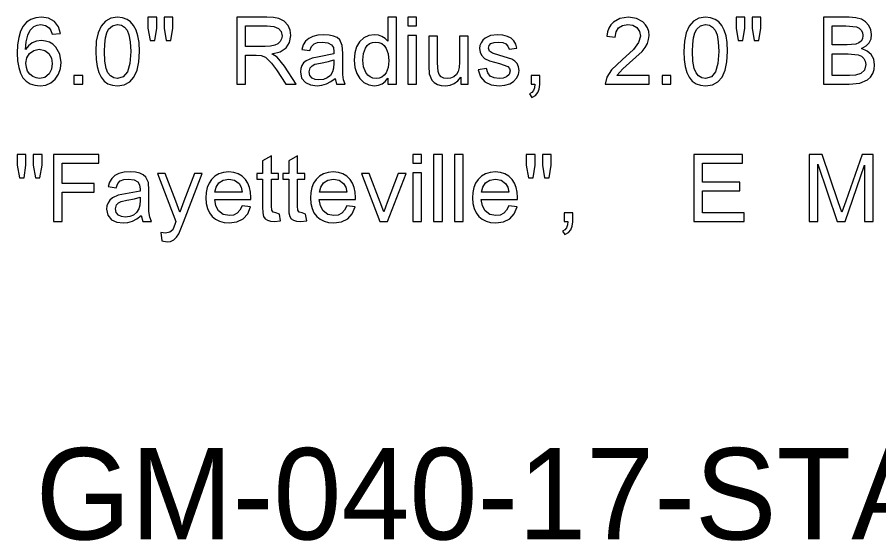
# Model space of a CAD drawing. Extents: x 620864 to 620948.6, y 415499.7 to 415559.1.
# Drawn here: x 620863.977 to 620867.745, y 415533.248 to 415535.538 of the extents above; entities that cross this region are included whole.
import ezdxf

# ---------------------------------------------------------------- set-up
doc = ezdxf.new("R2010")
doc.units = 0
doc.layers.add('SIGNS', color=7, linetype='Continuous')

msp = doc.modelspace()

# ---------------------------------------------------------------- linework, layer by layer
at = {"layer": 'SIGNS'}
for points in [[(620864.1658, 415535.4666), (620864.1569, 415535.4965), (620864.1392, 415535.5191), (620864.1138, 415535.5332), (620864.0822, 415535.538), (620864.0574, 415535.5356), (620864.036, 415535.5282), (620864.0177, 415535.5158), (620864.0029, 415535.4986), (620863.9913, 415535.4764), (620863.9832, 415535.4494), (620863.9782, 415535.4174), (620863.9766, 415535.3806), (620863.9781, 415535.3471), (620863.9829, 415535.3181), (620863.9908, 415535.2936), (620864.0018, 415535.2736), (620864.0159, 415535.258), (620864.0332, 415535.2469), (620864.0537, 415535.2403), (620864.0773, 415535.2381), (620864.1021, 415535.2413), (620864.124, 415535.2508), (620864.1428, 415535.2671), (620864.157, 415535.2891), (620864.1654, 415535.3134), (620864.1681, 415535.3396), (620864.1622, 415535.3763), (620864.145, 415535.4069), (620864.132, 415535.4195), (620864.1173, 415535.4287), (620864.1009, 415535.434), (620864.0827, 415535.4359), (620864.0614, 415535.4334), (620864.0426, 415535.4259), (620864.0263, 415535.4136), (620864.0126, 415535.3963), (620864.0152, 415535.4307), (620864.0224, 415535.4591), (620864.0338, 415535.481), (620864.0497, 415535.4968), (620864.064, 415535.5038), (620864.08, 415535.5061), (620864.1, 415535.5024), (620864.1162, 415535.4921), (620864.124, 415535.4807), (620864.1299, 415535.464), (620864.1658, 415535.4666)], [(620864.3197, 415535.3879), (620864.3212, 415535.3526), (620864.3257, 415535.3221), (620864.3331, 415535.2963), (620864.3437, 415535.2753), (620864.3571, 415535.2588), (620864.3735, 415535.2472), (620864.393, 415535.2403), (620864.4154, 415535.2381), (620864.4448, 415535.2425), (620864.4687, 415535.2553), (620864.4872, 415535.2765), (620864.5005, 415535.3058), (620864.5085, 415535.3429), (620864.5111, 415535.3879), (620864.5095, 415535.4272), (620864.5046, 415535.4573), (620864.4962, 415535.4816), (620864.4855, 415535.5016), (620864.4724, 415535.5172), (620864.4569, 415535.5285), (620864.4372, 415535.5358), (620864.4154, 415535.538), (620864.3858, 415535.5336), (620864.3622, 415535.5208), (620864.3435, 415535.4994), (620864.3302, 415535.4701), (620864.3223, 415535.4329), (620864.3197, 415535.3879)], [(620864.937, 415535.2445), (620864.9753, 415535.2445), (620864.9753, 415535.3721), (620865.0215, 415535.3721), (620865.0437, 415535.3708), (620865.0619, 415535.3635), (620865.0887, 415535.3374), (620865.1109, 415535.3073), (620865.1511, 415535.2445), (620865.1965, 415535.2445), (620865.1453, 415535.3243), (620865.113, 415535.3634), (620865.0895, 415535.378), (620865.1262, 415535.3873), (620865.1524, 415535.4038), (620865.1681, 415535.4273), (620865.1731, 415535.458), (620865.17, 415535.4812), (620865.1609, 415535.5022), (620865.1438, 415535.521), (620865.1202, 415535.5327), (620865.098, 415535.5367), (620865.0679, 415535.538), (620864.937, 415535.538), (620864.937, 415535.2445)], [(620865.5969, 415535.2445), (620865.6352, 415535.2445), (620865.6352, 415535.538), (620865.5969, 415535.538), (620865.5969, 415535.4332), (620865.5853, 415535.4455), (620865.5718, 415535.4544), (620865.5563, 415535.4597), (620865.5389, 415535.4615), (620865.5141, 415535.458), (620865.492, 415535.4476), (620865.4734, 415535.4307), (620865.4603, 415535.4088), (620865.4525, 415535.3817), (620865.45, 415535.3496), (620865.4529, 415535.3184), (620865.4612, 415535.2916), (620865.4746, 415535.2696), (620865.4927, 415535.2527), (620865.5147, 415535.2416), (620865.539, 415535.2381), (620865.557, 415535.2402), (620865.5726, 415535.2464), (620865.5859, 415535.2568), (620865.5969, 415535.2714), (620865.5969, 415535.2445)], [(620866.8917, 415535.3879), (620866.8932, 415535.3526), (620866.8977, 415535.3221), (620866.9052, 415535.2963), (620866.9158, 415535.2753), (620866.9292, 415535.2588), (620866.9456, 415535.2472), (620866.9651, 415535.2403), (620866.9875, 415535.2381), (620867.0169, 415535.2425), (620867.0407, 415535.2553), (620867.0593, 415535.2765), (620867.0726, 415535.3058), (620867.0806, 415535.3429), (620867.0832, 415535.3879), (620867.0815, 415535.4272), (620867.0767, 415535.4573), (620867.0683, 415535.4816), (620867.0576, 415535.5016), (620867.0444, 415535.5172), (620867.029, 415535.5285), (620867.0093, 415535.5358), (620866.9875, 415535.538), (620866.9579, 415535.5336), (620866.9343, 415535.5208), (620866.9156, 415535.4994), (620866.9023, 415535.4701), (620866.8943, 415535.4329), (620866.8917, 415535.3879)], [(620867.5027, 415535.2445), (620867.6155, 415535.2445), (620867.6625, 415535.2492), (620867.6956, 415535.2639), (620867.7088, 415535.2765), (620867.7184, 415535.2916), (620867.7241, 415535.3093), (620867.7261, 415535.3295), (620867.7225, 415535.3544), (620867.7119, 415535.3746), (620867.6943, 415535.3899), (620867.6696, 415535.4006), (620867.6888, 415535.4123), (620867.7025, 415535.4266), (620867.7107, 415535.4435), (620867.7133, 415535.4629), (620867.7101, 415535.4834), (620867.701, 415535.5023), (620867.6869, 415535.5181), (620867.6692, 415535.5291), (620867.6449, 415535.5358), (620867.6145, 415535.538), (620867.5027, 415535.538), (620867.5027, 415535.2445)], [(620864.358, 415535.388), (620864.3591, 415535.4209), (620864.3625, 415535.4481), (620864.3681, 415535.4695), (620864.3762, 415535.4855), (620864.3931, 415535.5011), (620864.415, 415535.5061), (620864.4319, 415535.5033), (620864.4459, 415535.4949), (620864.457, 415535.481), (620864.4652, 415535.4617), (620864.4709, 415535.4305), (620864.4729, 415535.388), (620864.4693, 415535.3362), (620864.4585, 415535.2993), (620864.4405, 415535.2772), (620864.4154, 415535.27), (620864.3985, 415535.2728), (620864.3846, 415535.2811), (620864.3735, 415535.295), (620864.3657, 415535.3144), (620864.3599, 415535.3455), (620864.358, 415535.388)], [(620864.9753, 415535.4104), (620864.9753, 415535.4997), (620865.0704, 415535.4997), (620865.0985, 415535.497), (620865.1187, 415535.4888), (620865.1308, 415535.475), (620865.1348, 415535.4559), (620865.1329, 415535.4432), (620865.1269, 415535.4315), (620865.117, 415535.4222), (620865.1027, 415535.4157), (620865.084, 415535.4117), (620865.0608, 415535.4104), (620864.9753, 415535.4104)], [(620866.93, 415535.388), (620866.9311, 415535.4209), (620866.9345, 415535.4481), (620866.9402, 415535.4695), (620866.9483, 415535.4855), (620866.9652, 415535.5011), (620866.9871, 415535.5061), (620867.0039, 415535.5033), (620867.018, 415535.4949), (620867.0291, 415535.481), (620867.0373, 415535.4617), (620867.0429, 415535.4305), (620867.045, 415535.388), (620867.0413, 415535.3362), (620867.0306, 415535.2993), (620867.0126, 415535.2772), (620866.9875, 415535.27), (620866.9705, 415535.2728), (620866.9567, 415535.2811), (620866.9456, 415535.295), (620866.9377, 415535.3144), (620866.9319, 415535.3455), (620866.93, 415535.388)], [(620867.541, 415535.4168), (620867.541, 415535.4997), (620867.6013, 415535.4997), (620867.6472, 415535.4959), (620867.6595, 415535.4903), (620867.6683, 415535.4821), (620867.6734, 415535.4711), (620867.675, 415535.4576), (620867.6729, 415535.4441), (620867.6672, 415535.4334), (620867.6576, 415535.4254), (620867.6443, 415535.42), (620867.6062, 415535.4168), (620867.541, 415535.4168)], [(620865.3664, 415535.2707), (620865.3736, 415535.2445), (620865.4114, 415535.2445), (620865.4038, 415535.2637), (620865.4002, 415535.2878), (620865.4, 415535.3334), (620865.4, 415535.3814), (620865.3982, 415535.4145), (620865.3869, 415535.4389), (620865.3754, 415535.4488), (620865.3599, 415535.4559), (620865.3406, 415535.46), (620865.3174, 415535.4615), (620865.2911, 415535.4595), (620865.2689, 415535.454), (620865.2515, 415535.4451), (620865.2377, 415535.4327), (620865.2276, 415535.4166), (620865.2211, 415535.3968), (620865.256, 415535.392), (620865.2636, 415535.4101), (620865.2746, 415535.4218), (620865.2897, 415535.4276), (620865.311, 415535.4295), (620865.3347, 415535.4263), (620865.3516, 415535.4174), (620865.3591, 415535.4051), (620865.3617, 415535.3865), (620865.3615, 415535.3772), (620865.2978, 415535.3648), (620865.2661, 415535.3594), (620865.2403, 415535.3477), (620865.2291, 415535.3378), (620865.2211, 415535.3264), (620865.2163, 415535.3133), (620865.2149, 415535.2986), (620865.2205, 415535.272), (620865.2368, 415535.2524), (620865.2594, 415535.2416), (620865.2878, 415535.2381), (620865.3085, 415535.2402), (620865.3285, 415535.2463), (620865.3478, 415535.2565), (620865.3664, 415535.2707)], [(620865.4883, 415535.3497), (620865.4911, 415535.3793), (620865.4997, 415535.403), (620865.5078, 415535.4146), (620865.518, 415535.4229), (620865.5301, 415535.4279), (620865.5443, 415535.4295), (620865.5587, 415535.4277), (620865.5712, 415535.4225), (620865.5818, 415535.4139), (620865.5904, 415535.4019), (620865.5992, 415535.3772), (620865.6022, 415535.3467), (620865.599, 415535.3184), (620865.59, 415535.2951), (620865.5815, 415535.2839), (620865.5714, 415535.2762), (620865.5595, 415535.2714), (620865.5458, 415535.27), (620865.5317, 415535.2717), (620865.5197, 415535.2766), (620865.5094, 415535.2849), (620865.5009, 415535.2965), (620865.4915, 415535.3205), (620865.4883, 415535.3497)], [(620864.0149, 415535.3371), (620864.0189, 415535.3604), (620864.0306, 415535.3797), (620864.0493, 415535.3932), (620864.073, 415535.3976), (620864.0971, 415535.3928), (620864.1154, 415535.3789), (620864.1263, 415535.3592), (620864.1298, 415535.3352), (620864.1262, 415535.311), (620864.116, 415535.2906), (620864.098, 415535.275), (620864.0744, 415535.27), (620864.059, 415535.2722), (620864.0447, 415535.2783), (620864.0314, 415535.2888), (620864.0222, 415535.3022), (620864.0166, 415535.3181), (620864.0149, 415535.3371)], [(620865.3617, 415535.3515), (620865.3617, 415535.3375), (620865.3602, 415535.3154), (620865.3559, 415535.2995), (620865.346, 415535.2837), (620865.3328, 415535.2725), (620865.3159, 415535.2658), (620865.2957, 415535.2636), (620865.2795, 415535.2656), (620865.2665, 415535.2716), (620865.2564, 415535.2832), (620865.2532, 415535.2991), (620865.2582, 415535.317), (620865.2663, 415535.3257), (620865.2784, 415535.332), (620865.3034, 415535.3371), (620865.3374, 415535.3437), (620865.3617, 415535.3515)], [(620867.541, 415535.2827), (620867.541, 415535.3785), (620867.6109, 415535.3785), (620867.655, 415535.3737), (620867.6694, 415535.3671), (620867.6797, 415535.3578), (620867.6858, 415535.3456), (620867.6878, 415535.3306), (620867.6818, 415535.3071), (620867.6668, 415535.2921), (620867.6435, 415535.284), (620867.6163, 415535.2827), (620867.541, 415535.2827)], [(620864.519, 415534.6707), (620864.5262, 415534.6445), (620864.564, 415534.6445), (620864.5564, 415534.6637), (620864.5528, 415534.6878), (620864.5526, 415534.7334), (620864.5526, 415534.7814), (620864.5508, 415534.8145), (620864.5395, 415534.8389), (620864.528, 415534.8488), (620864.5125, 415534.8559), (620864.4932, 415534.86), (620864.47, 415534.8615), (620864.4437, 415534.8595), (620864.4215, 415534.854), (620864.4041, 415534.8451), (620864.3903, 415534.8327), (620864.3802, 415534.8166), (620864.3737, 415534.7968), (620864.4086, 415534.792), (620864.4162, 415534.8101), (620864.4272, 415534.8218), (620864.4423, 415534.8276), (620864.4635, 415534.8295), (620864.4873, 415534.8263), (620864.5042, 415534.8174), (620864.5117, 415534.8051), (620864.5143, 415534.7865), (620864.5141, 415534.7772), (620864.4504, 415534.7648), (620864.4186, 415534.7594), (620864.3929, 415534.7477), (620864.3817, 415534.7378), (620864.3737, 415534.7264), (620864.3689, 415534.7133), (620864.3675, 415534.6986), (620864.3731, 415534.672), (620864.3894, 415534.6524), (620864.412, 415534.6416), (620864.4404, 415534.6381), (620864.461, 415534.6402), (620864.4811, 415534.6463), (620864.5003, 415534.6565), (620864.519, 415534.6707)], [(620864.9603, 415534.7132), (620864.9508, 415534.6942), (620864.9384, 415534.6807), (620864.9228, 415534.6727), (620864.9043, 415534.67), (620864.8776, 415534.6753), (620864.8572, 415534.6912), (620864.8452, 415534.7129), (620864.8402, 415534.7402), (620864.9984, 415534.7402), (620864.9986, 415534.7498), (620864.9971, 415534.7729), (620864.9926, 415534.7937), (620864.9851, 415534.8122), (620864.9747, 415534.8285), (620864.9602, 415534.8429), (620864.9432, 415534.8532), (620864.9236, 415534.8593), (620864.9016, 415534.8615), (620864.8787, 415534.8593), (620864.8587, 415534.8531), (620864.8412, 415534.8427), (620864.8265, 415534.8283), (620864.8157, 415534.8117), (620864.808, 415534.7928), (620864.8034, 415534.7715), (620864.8019, 415534.7479), (620864.8036, 415534.7231), (620864.8087, 415534.7014), (620864.8172, 415534.6825), (620864.8292, 415534.6668), (620864.8441, 415534.6542), (620864.8615, 415534.6452), (620864.8812, 415534.6399), (620864.9035, 415534.6381), (620864.9377, 415534.6425), (620864.9647, 415534.6556), (620864.9845, 415534.6776), (620864.9974, 415534.7085), (620864.9603, 415534.7132)], [(620865.4177, 415534.7132), (620865.4082, 415534.6942), (620865.3957, 415534.6807), (620865.3802, 415534.6727), (620865.3617, 415534.67), (620865.335, 415534.6753), (620865.3145, 415534.6912), (620865.3026, 415534.7129), (620865.2976, 415534.7402), (620865.4558, 415534.7402), (620865.456, 415534.7498), (620865.4545, 415534.7729), (620865.45, 415534.7937), (620865.4425, 415534.8122), (620865.432, 415534.8285), (620865.4176, 415534.8429), (620865.4006, 415534.8532), (620865.381, 415534.8593), (620865.3589, 415534.8615), (620865.3361, 415534.8593), (620865.316, 415534.8531), (620865.2986, 415534.8427), (620865.2838, 415534.8283), (620865.273, 415534.8117), (620865.2654, 415534.7928), (620865.2608, 415534.7715), (620865.2593, 415534.7479), (620865.261, 415534.7231), (620865.2661, 415534.7014), (620865.2745, 415534.6825), (620865.2866, 415534.6668), (620865.3015, 415534.6542), (620865.3188, 415534.6452), (620865.3386, 415534.6399), (620865.3609, 415534.6381), (620865.395, 415534.6425), (620865.4221, 415534.6556), (620865.4419, 415534.6776), (620865.4548, 415534.7085), (620865.4177, 415534.7132)], [(620866.1262, 415534.7132), (620866.1167, 415534.6942), (620866.1043, 415534.6807), (620866.0887, 415534.6727), (620866.0703, 415534.67), (620866.0435, 415534.6753), (620866.0231, 415534.6912), (620866.0111, 415534.7129), (620866.0061, 415534.7402), (620866.1643, 415534.7402), (620866.1645, 415534.7498), (620866.163, 415534.7729), (620866.1585, 415534.7937), (620866.151, 415534.8122), (620866.1406, 415534.8285), (620866.1261, 415534.8429), (620866.1091, 415534.8532), (620866.0895, 415534.8593), (620866.0675, 415534.8615), (620866.0446, 415534.8593), (620866.0246, 415534.8531), (620866.0071, 415534.8427), (620865.9924, 415534.8283), (620865.9816, 415534.8117), (620865.9739, 415534.7928), (620865.9693, 415534.7715), (620865.9678, 415534.7479), (620865.9695, 415534.7231), (620865.9746, 415534.7014), (620865.9831, 415534.6825), (620865.9951, 415534.6668), (620866.01, 415534.6542), (620866.0274, 415534.6452), (620866.0471, 415534.6399), (620866.0694, 415534.6381), (620866.1036, 415534.6425), (620866.1306, 415534.6556), (620866.1505, 415534.6776), (620866.1633, 415534.7085), (620866.1262, 415534.7132)], [(620864.8413, 415534.7721), (620864.8466, 415534.7947), (620864.859, 415534.813), (620864.878, 415534.8254), (620864.902, 415534.8295), (620864.9269, 415534.8246), (620864.9467, 415534.81), (620864.9557, 415534.7941), (620864.9604, 415534.7721), (620864.8413, 415534.7721)], [(620865.2987, 415534.7721), (620865.304, 415534.7947), (620865.3163, 415534.813), (620865.3354, 415534.8254), (620865.3593, 415534.8295), (620865.3843, 415534.8246), (620865.4041, 415534.81), (620865.4131, 415534.7941), (620865.4178, 415534.7721), (620865.2987, 415534.7721)], [(620866.0072, 415534.7721), (620866.0125, 415534.7947), (620866.0249, 415534.813), (620866.0439, 415534.8254), (620866.0679, 415534.8295), (620866.0928, 415534.8246), (620866.1126, 415534.81), (620866.1216, 415534.7941), (620866.1263, 415534.7721), (620866.0072, 415534.7721)], [(620864.5143, 415534.7515), (620864.5143, 415534.7375), (620864.5128, 415534.7154), (620864.5085, 415534.6995), (620864.4986, 415534.6837), (620864.4854, 415534.6725), (620864.4685, 415534.6658), (620864.4483, 415534.6636), (620864.4321, 415534.6656), (620864.419, 415534.6716), (620864.409, 415534.6832), (620864.4058, 415534.6991), (620864.4108, 415534.717), (620864.4189, 415534.7257), (620864.431, 415534.732), (620864.456, 415534.7371), (620864.4899, 415534.7437), (620864.5143, 415534.7515)]]:
    msp.add_lwpolyline(points, dxfattribs=at)
for points in [[(620864.5578, 415535.4359), (620864.5783, 415535.4359), (620864.5867, 415535.4908), (620864.5867, 415535.538), (620864.5484, 415535.538), (620864.5484, 415535.4908)], [(620864.6278, 415535.4359), (620864.648, 415535.4359), (620864.6569, 415535.4908), (620864.6569, 415535.538), (620864.6187, 415535.538), (620864.6187, 415535.4908)], [(620865.6852, 415535.4997), (620865.7235, 415535.4997), (620865.7235, 415535.538), (620865.6852, 415535.538)], [(620866.7402, 415535.2827), (620866.5988, 415535.2827), (620866.6247, 415535.3125), (620866.6548, 415535.3382), (620866.7095, 415535.3888), (620866.7228, 415535.4061), (620866.7325, 415535.4235), (620866.7382, 415535.4407), (620866.7402, 415535.4581), (620866.7385, 415535.4757), (620866.7334, 415535.4915), (620866.7249, 415535.5053), (620866.7132, 415535.5174), (620866.6847, 415535.5329), (620866.6497, 415535.538), (620866.6126, 415535.5327), (620866.5838, 415535.5166), (620866.5727, 415535.5046), (620866.5643, 415535.4905), (620866.5586, 415535.4737), (620866.5555, 415535.4548), (620866.5917, 415535.4511), (620866.5955, 415535.4737), (620866.6067, 415535.4913), (620866.6244, 415535.5024), (620866.6478, 415535.5061), (620866.6687, 415535.5026), (620866.6858, 415535.4925), (620866.6978, 415535.4762), (620866.7019, 415535.4559), (620866.6944, 415535.428), (620866.6723, 415535.3971), (620866.6222, 415535.3516), (620866.5759, 415535.3078), (620866.5551, 415535.2754), (620866.5487, 415535.2445), (620866.7402, 415535.2445)], [(620867.1299, 415535.4359), (620867.1504, 415535.4359), (620867.1588, 415535.4908), (620867.1588, 415535.538), (620867.1205, 415535.538), (620867.1205, 415535.4908)], [(620867.1999, 415535.4359), (620867.22, 415535.4359), (620867.229, 415535.4908), (620867.229, 415535.538), (620867.1907, 415535.538), (620867.1907, 415535.4908)], [(620865.6852, 415535.2445), (620865.7235, 415535.2445), (620865.7235, 415535.4578), (620865.6852, 415535.4578)], [(620865.9926, 415535.308), (620866.0029, 415535.2772), (620866.0217, 415535.2553), (620866.0488, 415535.2423), (620866.0845, 415535.2381), (620866.1095, 415535.2402), (620866.1304, 415535.2463), (620866.1474, 415535.2566), (620866.1605, 415535.2711), (620866.1687, 415535.2876), (620866.1713, 415535.305), (620866.1691, 415535.3214), (620866.1631, 415535.3352), (620866.1532, 415535.3461), (620866.1393, 415535.3544), (620866.0867, 415535.371), (620866.0552, 415535.3802), (620866.0415, 415535.3897), (620866.0373, 415535.4023), (620866.0401, 415535.4142), (620866.0486, 415535.4228), (620866.0626, 415535.4279), (620866.0822, 415535.4295), (620866.0999, 415535.4274), (620866.1135, 415535.4215), (620866.1226, 415535.4116), (620866.1274, 415535.3979), (620866.1617, 415535.4026), (620866.1566, 415535.4205), (620866.1482, 415535.435), (620866.1363, 415535.4463), (620866.1212, 415535.4544), (620866.1005, 415535.4597), (620866.0774, 415535.4615), (620866.0467, 415535.4577), (620866.0232, 415535.4467), (620866.0125, 415535.4372), (620866.005, 415535.4263), (620866.0005, 415535.4141), (620865.999, 415535.4005), (620866.0009, 415535.3854), (620866.0069, 415535.3721), (620866.0205, 415535.3578), (620866.0422, 415535.3468), (620866.0853, 415535.3349), (620866.1223, 415535.3227), (620866.1303, 415535.3144), (620866.133, 415535.3036), (620866.1288, 415535.2881), (620866.1165, 415535.2772), (620866.1016, 415535.2718), (620866.0838, 415535.27), (620866.0618, 415535.2727), (620866.0454, 415535.2809), (620866.0342, 415535.2945), (620866.0285, 415535.3137)], [(620865.917, 415535.2445), (620865.9489, 415535.2445), (620865.9489, 415535.4551), (620865.9106, 415535.4551), (620865.9106, 415535.342), (620865.9091, 415535.318), (620865.9048, 415535.3006), (620865.8971, 415535.2877), (620865.8857, 415535.278), (620865.8716, 415535.2718), (620865.8568, 415535.27), (620865.8419, 415535.272), (620865.8303, 415535.2776), (620865.822, 415535.287), (620865.817, 415535.3002), (620865.8149, 415535.338), (620865.8149, 415535.4551), (620865.7766, 415535.4551), (620865.7766, 415535.3236), (620865.7788, 415535.29), (620865.7898, 415535.2632), (620865.8004, 415535.2521), (620865.814, 415535.2444), (620865.8302, 415535.2396), (620865.8494, 415535.2381), (620865.8696, 415535.2404), (620865.8877, 415535.2474), (620865.9034, 415535.2592), (620865.917, 415535.2758)], [(620864.2245, 415535.2445), (620864.2628, 415535.2445), (620864.2628, 415535.2827), (620864.2245, 415535.2827)], [(620866.2238, 415535.2445), (620866.2403, 415535.2445), (620866.2385, 415535.2294), (620866.2341, 415535.2174), (620866.227, 415535.2083), (620866.2174, 415535.2023), (620866.2276, 415535.187), (620866.2426, 415535.1959), (620866.2534, 415535.2082), (620866.2599, 415535.2238), (620866.2621, 415535.2431), (620866.2621, 415535.2827), (620866.2238, 415535.2827)], [(620866.7966, 415535.2445), (620866.8349, 415535.2445), (620866.8349, 415535.2827), (620866.7966, 415535.2827)], [(620863.986, 415534.8359), (620864.0065, 415534.8359), (620864.0149, 415534.8908), (620864.0149, 415534.938), (620863.9766, 415534.938), (620863.9766, 415534.8908)], [(620864.056, 415534.8359), (620864.0761, 415534.8359), (620864.0851, 415534.8908), (620864.0851, 415534.938), (620864.0468, 415534.938), (620864.0468, 415534.8908)], [(620864.1354, 415534.6445), (620864.1737, 415534.6445), (620864.1737, 415534.7721), (620864.3126, 415534.7721), (620864.3126, 415534.8104), (620864.1737, 415534.8104), (620864.1737, 415534.8997), (620864.334, 415534.8997), (620864.334, 415534.938), (620864.1354, 415534.938)], [(620865.1232, 415534.6768), (620865.108, 415534.6827), (620865.0959, 415534.6852), (620865.0901, 415534.694), (620865.0881, 415534.7108), (620865.0881, 415534.8295), (620865.12, 415534.8295), (620865.12, 415534.8551), (620865.0881, 415534.8551), (620865.0881, 415534.9317), (620865.0498, 415534.9093), (620865.0498, 415534.8551), (620865.0243, 415534.8551), (620865.0243, 415534.8295), (620865.0498, 415534.8295), (620865.0498, 415534.7086), (620865.0509, 415534.6821), (620865.0543, 415534.6666), (620865.0608, 415534.6567), (620865.0708, 415534.6497), (620865.084, 415534.6456), (620865.1007, 415534.6445), (620865.1283, 415534.6474)], [(620865.2375, 415534.6768), (620865.2223, 415534.6827), (620865.2102, 415534.6852), (620865.2043, 415534.694), (620865.2024, 415534.7108), (620865.2024, 415534.8295), (620865.2343, 415534.8295), (620865.2343, 415534.8551), (620865.2024, 415534.8551), (620865.2024, 415534.9317), (620865.1641, 415534.9093), (620865.1641, 415534.8551), (620865.1386, 415534.8551), (620865.1386, 415534.8295), (620865.1641, 415534.8295), (620865.1641, 415534.7086), (620865.1652, 415534.6821), (620865.1686, 415534.6666), (620865.1751, 415534.6567), (620865.1851, 415534.6497), (620865.1983, 415534.6456), (620865.215, 415534.6445), (620865.2426, 415534.6474)], [(620865.7065, 415534.8997), (620865.7448, 415534.8997), (620865.7448, 415534.938), (620865.7065, 415534.938)], [(620865.7979, 415534.6445), (620865.8361, 415534.6445), (620865.8361, 415534.938), (620865.7979, 415534.938)], [(620865.8892, 415534.6445), (620865.9275, 415534.6445), (620865.9275, 415534.938), (620865.8892, 415534.938)], [(620866.2123, 415534.8359), (620866.2329, 415534.8359), (620866.2413, 415534.8908), (620866.2413, 415534.938), (620866.203, 415534.938), (620866.203, 415534.8908)], [(620866.2824, 415534.8359), (620866.3025, 415534.8359), (620866.3115, 415534.8908), (620866.3115, 415534.938), (620866.2732, 415534.938), (620866.2732, 415534.8908)], [(620866.9356, 415534.6445), (620867.1554, 415534.6445), (620867.1554, 415534.6827), (620866.9739, 415534.6827), (620866.9739, 415534.7785), (620867.1374, 415534.7785), (620867.1374, 415534.8168), (620866.9739, 415534.8168), (620866.9739, 415534.8997), (620867.1485, 415534.8997), (620867.1485, 415534.938), (620866.9356, 415534.938)], [(620867.4397, 415534.6445), (620867.478, 415534.6445), (620867.478, 415534.8951), (620867.5625, 415534.6445), (620867.5976, 415534.6445), (620867.6822, 415534.8909), (620867.6822, 415534.6445), (620867.7205, 415534.6445), (620867.7205, 415534.938), (620867.6715, 415534.938), (620867.601, 415534.7329), (620867.5824, 415534.6851), (620867.5671, 415534.7301), (620867.4972, 415534.938), (620867.4397, 415534.938)], [(620864.6087, 415534.5599), (620864.6321, 415534.5551), (620864.6476, 415534.5573), (620864.6615, 415534.564), (620864.6736, 415534.5752), (620864.6839, 415534.5908), (620864.7042, 415534.6409), (620864.7854, 415534.8551), (620864.7512, 415534.8551), (620864.705, 415534.7329), (620864.6882, 415534.6848), (620864.6709, 415534.7333), (620864.6242, 415534.8551), (620864.5899, 415534.8551), (620864.6709, 415534.6439), (620864.6677, 415534.6351), (620864.6566, 415534.6085), (620864.6447, 415534.5974), (620864.6255, 415534.5934), (620864.6047, 415534.5963)], [(620865.5629, 415534.6445), (620865.5966, 415534.6445), (620865.6773, 415534.8551), (620865.6431, 415534.8551), (620865.5941, 415534.7271), (620865.5793, 415534.687), (620865.5643, 415534.7295), (620865.5158, 415534.8551), (620865.4817, 415534.8551)], [(620865.7065, 415534.6445), (620865.7448, 415534.6445), (620865.7448, 415534.8578), (620865.7065, 415534.8578)], [(620866.3681, 415534.6445), (620866.3847, 415534.6445), (620866.3828, 415534.6294), (620866.3784, 415534.6174), (620866.3713, 415534.6083), (620866.3618, 415534.6023), (620866.372, 415534.587), (620866.387, 415534.5959), (620866.3978, 415534.6082), (620866.4042, 415534.6238), (620866.4064, 415534.6431), (620866.4064, 415534.6827), (620866.3681, 415534.6827)]]:
    msp.add_lwpolyline(points, close=True, dxfattribs=at)

# ---------------------------------------------------------------- texts
msp.add_text('GM-040-17-STA193+50EB', height=0.4, dxfattribs=at).set_placement((620864.0572, 415533.2533))

doc.saveas('drawing.dxf')
